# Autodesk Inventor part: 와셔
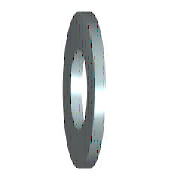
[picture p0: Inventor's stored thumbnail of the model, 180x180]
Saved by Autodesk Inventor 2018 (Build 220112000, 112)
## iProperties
Created: 2012-02
Part Number: 와셔
Material: 강철, 연강
Description: 평면 와셔
Document SubType Name: Modeling
Standard: KS B 1326
Designer: mduedu
Standards Organization: KS
Language: ko-KR
Size Designation: 8x15.5
Categories: <MemberInstance><Categories><Category DisplayName="조임쇠" InternalName="e4da775c-781d-43d5-af7c-5136215cf5a6" Mnemonic="FSTN"><Category DisplayName="와셔" InternalN
Density: 1 g/cm^3
Appearance: 파란색 - 벽 페인트 - 광택
IsCustomPart: 1
Author: mduedu
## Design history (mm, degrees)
sketch "스케치"
  geometry: C1 r 7.75 at (0, 0); C2 r 4.2 at (0, 0); 1 further point
  constraints: 2 centre point, 2 coincident
  dimensions: "d0" = 8.4 diameter of C2 (= SD1); "d1" = 15.5 diameter of C1 (= SD2)
extrude "본체" new body sketch "스케치" distance "d2" = 1.6 (= SD); taper "d3" = 0 deg
workaxis "Work Axis1"
workplane "Work Plane1"
body "Solid1"
other parameters: "SD1" = 8.4 [user parameter; used in 1 equation term], "SD2" = 15.5 [user parameter; used in 1 equation term], "SD" = 1.6 [user parameter; used in 1 equation term], "d4" = 0, "d5" = 0, "d6" = 0, "d7" = 0, "NND" = 8 [user parameter]
